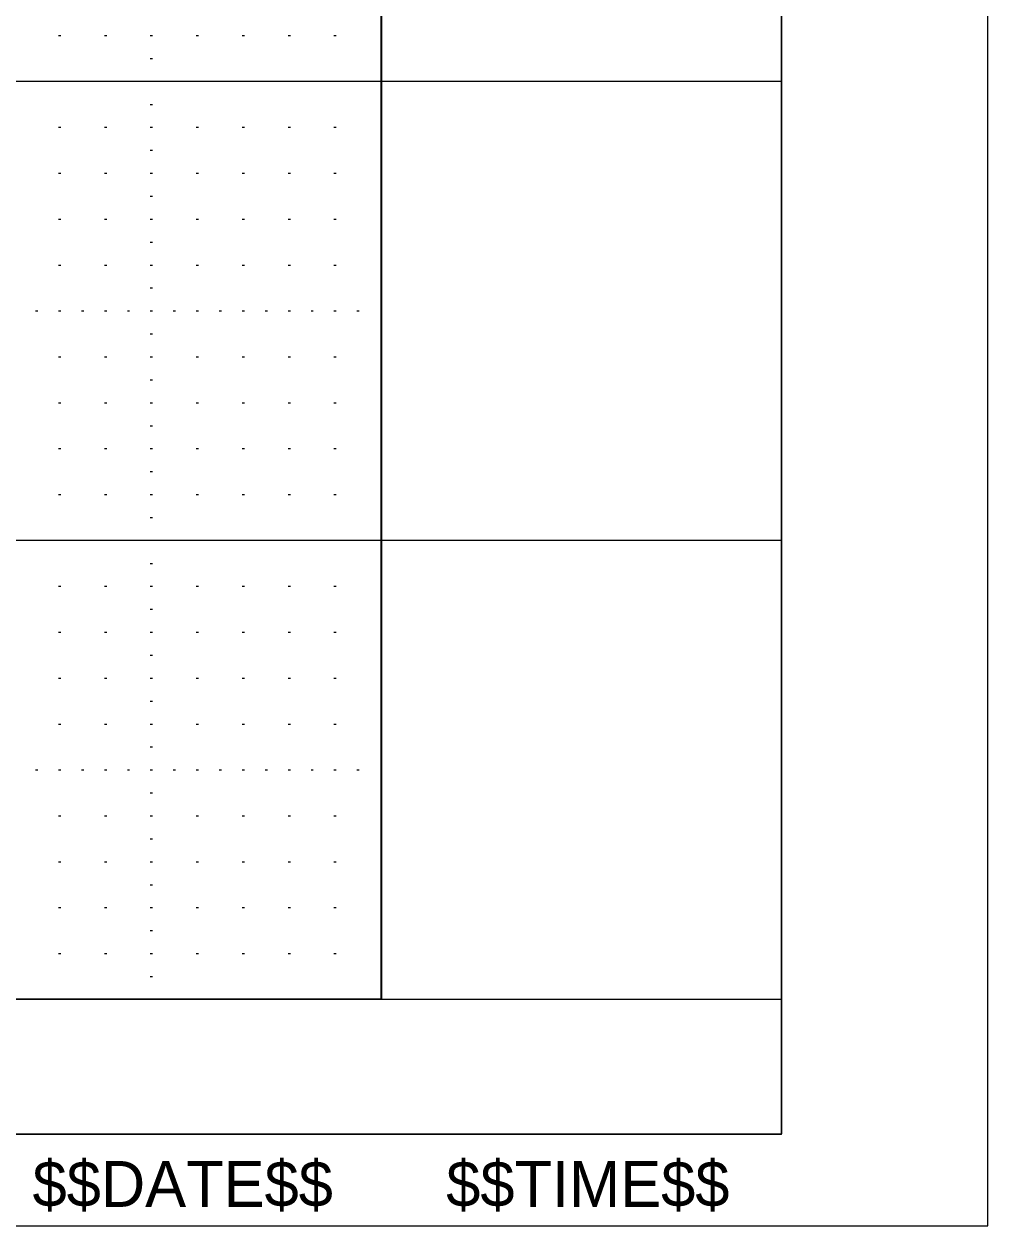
# Model space of a CAD drawing. Extents: x -1.3 to 32.1, y -0.2 to 20.7.
# Drawn here: x 29.967 to 32.067, y -0.2 to 2.418 of the extents above; entities that cross this region are included whole.
import ezdxf

# ---------------------------------------------------------------- set-up
doc = ezdxf.new("R2010")
doc.units = 0
for name, color, linetype in [('Level 1', 7, 'Continuous'), ('Level 37', 7, 'Continuous'), ('Level 4', 7, 'Continuous'), ('Level 48', 7, 'Continuous'), ('Level 5', 7, 'Continuous'), ('Level 62', 7, 'Continuous'), ('Level 63', 7, 'Continuous')]:
    doc.layers.add(name, color=color, linetype=linetype)

msp = doc.modelspace()

# ---------------------------------------------------------------- linework, layer by layer
at = {"layer": 'Level 1'}
for q in [(31.617, 20.545), (-0.001, -0.001)]:
    msp.add_line((31.617, -0.001), q, dxfattribs=at)
at = {"layer": 'Level 37'}
for p, q in [((30.746, 10.2935), (30.746, 0.2935)), ((30.746, 0.2935), (2.464, 0.2935))]:
    msp.add_line(p, q, dxfattribs=at)
at = {"layer": 'Level 4'}
for p, q in [((30.745, 0.293), (30.745, 10.293)), ((31.617, 2.293), (-0.001, 2.293)), ((31.617, 1.293), (-0.001, 1.293)), ((31.617, 0.293), (2.463, 0.293))]:
    msp.add_line(p, q, dxfattribs=at)
at = {"layer": 'Level 5'}
for p, q in [((30.0425, 2.393), (30.0475, 2.393)), ((30.1425, 2.393), (30.1475, 2.393)), ((30.2425, 2.393), (30.2475, 2.393)), ((30.3425, 2.393), (30.3475, 2.393)), ((30.4425, 2.393), (30.4475, 2.393)), ((30.5425, 2.393), (30.5475, 2.393)), ((30.6425, 2.393), (30.6475, 2.393)), ((30.2425, 2.343), (30.2475, 2.343)), ((30.2425, 2.243), (30.2475, 2.243)), ((30.0425, 2.193), (30.0475, 2.193)), ((30.1425, 2.193), (30.1475, 2.193)), ((30.2425, 2.193), (30.2475, 2.193)), ((30.3425, 2.193), (30.3475, 2.193)), ((30.4425, 2.193), (30.4475, 2.193)), ((30.5425, 2.193), (30.5475, 2.193)), ((30.6425, 2.193), (30.6475, 2.193)), ((30.2425, 2.143), (30.2475, 2.143)), ((30.0425, 2.093), (30.0475, 2.093)), ((30.1425, 2.093), (30.1475, 2.093)), ((30.2425, 2.093), (30.2475, 2.093)), ((30.3425, 2.093), (30.3475, 2.093)), ((30.4425, 2.093), (30.4475, 2.093)), ((30.5425, 2.093), (30.5475, 2.093)), ((30.6425, 2.093), (30.6475, 2.093)), ((30.2425, 2.043), (30.2475, 2.043)), ((30.0425, 1.993), (30.0475, 1.993)), ((30.1425, 1.993), (30.1475, 1.993)), ((30.2425, 1.993), (30.2475, 1.993)), ((30.3425, 1.993), (30.3475, 1.993)), ((30.4425, 1.993), (30.4475, 1.993)), ((30.5425, 1.993), (30.5475, 1.993)), ((30.6425, 1.993), (30.6475, 1.993)), ((30.2425, 1.943), (30.2475, 1.943)), ((30.0425, 1.893), (30.0475, 1.893)), ((30.1425, 1.893), (30.1475, 1.893)), ((30.2425, 1.893), (30.2475, 1.893)), ((30.3425, 1.893), (30.3475, 1.893)), ((30.4425, 1.893), (30.4475, 1.893)), ((30.5425, 1.893), (30.5475, 1.893)), ((30.6425, 1.893), (30.6475, 1.893)), ((30.2425, 1.843), (30.2475, 1.843)), ((29.9925, 1.793), (29.9975, 1.793)), ((30.0425, 1.793), (30.0475, 1.793)), ((30.0925, 1.793), (30.0975, 1.793)), ((30.1425, 1.793), (30.1475, 1.793)), ((30.1925, 1.793), (30.1975, 1.793)), ((30.2425, 1.793), (30.2475, 1.793)), ((30.2925, 1.793), (30.2975, 1.793)), ((30.3425, 1.793), (30.3475, 1.793)), ((30.3925, 1.793), (30.3975, 1.793)), ((30.4425, 1.793), (30.4475, 1.793)), ((30.4925, 1.793), (30.4975, 1.793)), ((30.5425, 1.793), (30.5475, 1.793)), ((30.5925, 1.793), (30.5975, 1.793)), ((30.6425, 1.793), (30.6475, 1.793)), ((30.6925, 1.793), (30.6975, 1.793)), ((30.2425, 1.743), (30.2475, 1.743)), ((30.0425, 1.693), (30.0475, 1.693)), ((30.1425, 1.693), (30.1475, 1.693)), ((30.2425, 1.693), (30.2475, 1.693)), ((30.3425, 1.693), (30.3475, 1.693)), ((30.4425, 1.693), (30.4475, 1.693)), ((30.5425, 1.693), (30.5475, 1.693)), ((30.6425, 1.693), (30.6475, 1.693)), ((30.2425, 1.643), (30.2475, 1.643)), ((30.0425, 1.593), (30.0475, 1.593)), ((30.1425, 1.593), (30.1475, 1.593)), ((30.2425, 1.593), (30.2475, 1.593)), ((30.3425, 1.593), (30.3475, 1.593)), ((30.4425, 1.593), (30.4475, 1.593)), ((30.5425, 1.593), (30.5475, 1.593)), ((30.6425, 1.593), (30.6475, 1.593)), ((30.2425, 1.543), (30.2475, 1.543)), ((30.0425, 1.493), (30.0475, 1.493)), ((30.1425, 1.493), (30.1475, 1.493)), ((30.2425, 1.493), (30.2475, 1.493)), ((30.3425, 1.493), (30.3475, 1.493)), ((30.4425, 1.493), (30.4475, 1.493)), ((30.5425, 1.493), (30.5475, 1.493)), ((30.6425, 1.493), (30.6475, 1.493)), ((30.2425, 1.443), (30.2475, 1.443)), ((30.0425, 1.393), (30.0475, 1.393)), ((30.1425, 1.393), (30.1475, 1.393)), ((30.2425, 1.393), (30.2475, 1.393)), ((30.3425, 1.393), (30.3475, 1.393)), ((30.4425, 1.393), (30.4475, 1.393)), ((30.5425, 1.393), (30.5475, 1.393)), ((30.6425, 1.393), (30.6475, 1.393)), ((30.2425, 1.343), (30.2475, 1.343)), ((30.2425, 1.243), (30.2475, 1.243)), ((30.0425, 1.193), (30.0475, 1.193)), ((30.1425, 1.193), (30.1475, 1.193)), ((30.2425, 1.193), (30.2475, 1.193)), ((30.3425, 1.193), (30.3475, 1.193)), ((30.4425, 1.193), (30.4475, 1.193)), ((30.5425, 1.193), (30.5475, 1.193)), ((30.6425, 1.193), (30.6475, 1.193)), ((30.2425, 1.143), (30.2475, 1.143)), ((30.0425, 1.093), (30.0475, 1.093)), ((30.1425, 1.093), (30.1475, 1.093)), ((30.2425, 1.093), (30.2475, 1.093)), ((30.3425, 1.093), (30.3475, 1.093)), ((30.4425, 1.093), (30.4475, 1.093)), ((30.5425, 1.093), (30.5475, 1.093)), ((30.6425, 1.093), (30.6475, 1.093)), ((30.2425, 1.043), (30.2475, 1.043)), ((30.0425, 0.993), (30.0475, 0.993)), ((30.1425, 0.993), (30.1475, 0.993)), ((30.2425, 0.993), (30.2475, 0.993)), ((30.3425, 0.993), (30.3475, 0.993)), ((30.4425, 0.993), (30.4475, 0.993)), ((30.5425, 0.993), (30.5475, 0.993)), ((30.6425, 0.993), (30.6475, 0.993)), ((30.2425, 0.943), (30.2475, 0.943)), ((30.0425, 0.893), (30.0475, 0.893)), ((30.1425, 0.893), (30.1475, 0.893)), ((30.2425, 0.893), (30.2475, 0.893)), ((30.3425, 0.893), (30.3475, 0.893)), ((30.4425, 0.893), (30.4475, 0.893)), ((30.5425, 0.893), (30.5475, 0.893)), ((30.6425, 0.893), (30.6475, 0.893)), ((30.2425, 0.843), (30.2475, 0.843)), ((29.9925, 0.793), (29.9975, 0.793)), ((30.0425, 0.793), (30.0475, 0.793)), ((30.0925, 0.793), (30.0975, 0.793)), ((30.1425, 0.793), (30.1475, 0.793)), ((30.1925, 0.793), (30.1975, 0.793)), ((30.2425, 0.793), (30.2475, 0.793)), ((30.2925, 0.793), (30.2975, 0.793)), ((30.3425, 0.793), (30.3475, 0.793)), ((30.3925, 0.793), (30.3975, 0.793)), ((30.4425, 0.793), (30.4475, 0.793)), ((30.4925, 0.793), (30.4975, 0.793)), ((30.5425, 0.793), (30.5475, 0.793)), ((30.5925, 0.793), (30.5975, 0.793)), ((30.6425, 0.793), (30.6475, 0.793)), ((30.6925, 0.793), (30.6975, 0.793)), ((30.2425, 0.743), (30.2475, 0.743)), ((30.0425, 0.693), (30.0475, 0.693)), ((30.1425, 0.693), (30.1475, 0.693)), ((30.2425, 0.693), (30.2475, 0.693)), ((30.3425, 0.693), (30.3475, 0.693)), ((30.4425, 0.693), (30.4475, 0.693)), ((30.5425, 0.693), (30.5475, 0.693)), ((30.6425, 0.693), (30.6475, 0.693)), ((30.2425, 0.643), (30.2475, 0.643)), ((30.0425, 0.593), (30.0475, 0.593)), ((30.1425, 0.593), (30.1475, 0.593)), ((30.2425, 0.593), (30.2475, 0.593)), ((30.3425, 0.593), (30.3475, 0.593)), ((30.4425, 0.593), (30.4475, 0.593)), ((30.5425, 0.593), (30.5475, 0.593)), ((30.6425, 0.593), (30.6475, 0.593)), ((30.2425, 0.543), (30.2475, 0.543)), ((30.0425, 0.493), (30.0475, 0.493)), ((30.1425, 0.493), (30.1475, 0.493)), ((30.2425, 0.493), (30.2475, 0.493)), ((30.3425, 0.493), (30.3475, 0.493)), ((30.4425, 0.493), (30.4475, 0.493)), ((30.5425, 0.493), (30.5475, 0.493)), ((30.6425, 0.493), (30.6475, 0.493)), ((30.2425, 0.443), (30.2475, 0.443)), ((30.0425, 0.393), (30.0475, 0.393)), ((30.1425, 0.393), (30.1475, 0.393)), ((30.2425, 0.393), (30.2475, 0.393)), ((30.3425, 0.393), (30.3475, 0.393)), ((30.4425, 0.393), (30.4475, 0.393)), ((30.5425, 0.393), (30.5475, 0.393)), ((30.6425, 0.393), (30.6475, 0.393)), ((30.2425, 0.343), (30.2475, 0.343))]:
    msp.add_line(p, q, dxfattribs=at)
at = {"layer": 'Level 62'}
for p, q in [((31.618, 0), (31.618, 10.294)), ((2.4642, 0), (31.618, 0))]:
    msp.add_line(p, q, dxfattribs=at)
at = {"layer": 'Level 63'}
msp.add_lwpolyline([(-1.263, -0.2005), (32.067, -0.2005), (32.067, 20.7465), (-1.263, 20.7465)], close=True, dxfattribs=at)

# ---------------------------------------------------------------- texts
at = {"layer": 'Level 48'}
for s, p in [('$$DATE$$', (29.986, -0.159)), ('$$TIME$$', (30.887, -0.159))]:
    msp.add_text(s, height=0.1, dxfattribs=at).set_placement(p)

doc.saveas('drawing.dxf')
